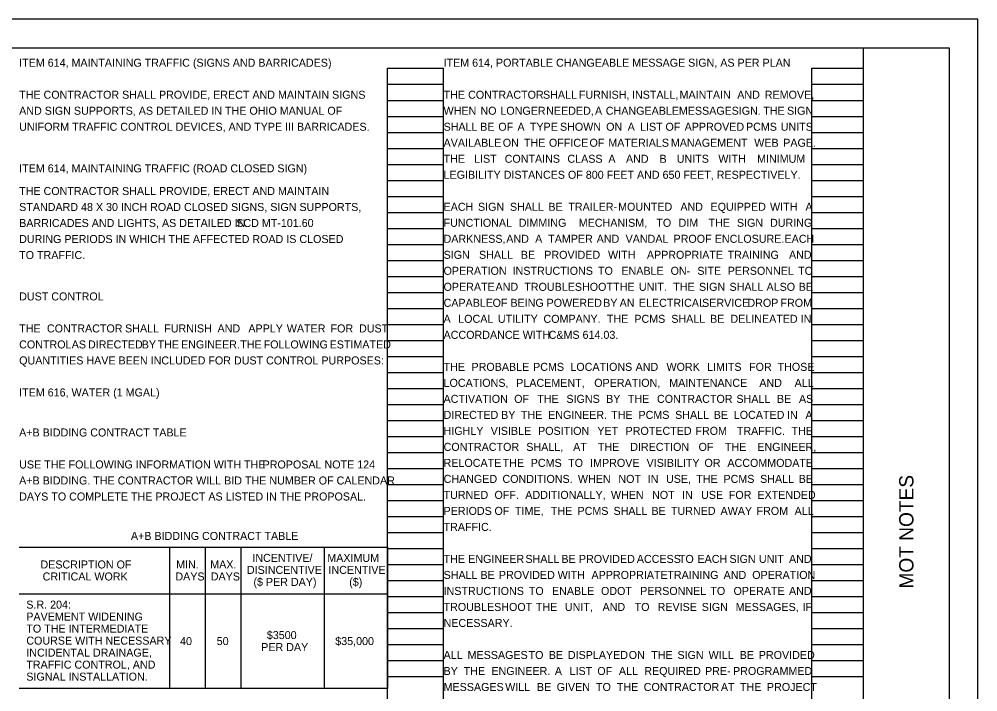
# Model space of a CAD drawing. Extents: x 0 to 34, y 0 to 22.
# Drawn here: x 17.24 to 34, y 10.23 to 22 of the extents above; entities that cross this region are included whole.
import ezdxf

# ---------------------------------------------------------------- set-up
doc = ezdxf.new("R2010")
doc.units = 0
for name, color, linetype in [('SH_Border', 7, 'Continuous'), ('SH_Cut_Line', 7, 'Continuous'), ('SH_Data', 7, 'Continuous'), ('SH_Text', 7, 'Continuous'), ('TX_P_1', 7, 'Continuous')]:
    doc.layers.add(name, color=color, linetype=linetype)

msp = doc.modelspace()

# ---------------------------------------------------------------- linework, layer by layer
at = {"layer": 'SH_Border'}
msp.add_line((32, 0.5), (32, 21.5), dxfattribs=at)
msp.add_lwpolyline([(1.5, 21.5), (33.5, 21.5), (33.5, 0.5), (1.5, 0.5)], close=True, dxfattribs=at)
at = {"layer": 'SH_Cut_Line'}
msp.add_lwpolyline([(0, 0), (34, 0), (34, 22), (0, 22)], close=True, dxfattribs=at)
at = {"layer": 'SH_Data'}
for p, q in [((23.68, 0.98), (23.68, 21.14)), ((23.68, 21.14), (24.66, 21.14)), ((24.66, 0.98), (24.66, 21.14)), ((31.1, 0.98), (31.1, 21.14)), ((31.1, 21.14), (32, 21.14)), ((32, 0.98), (32, 21.14)), ((23.68, 20.86), (24.66, 20.86)), ((31.1, 20.86), (32, 20.86)), ((23.68, 20.58), (24.66, 20.58)), ((31.1, 20.58), (32, 20.58)), ((23.68, 20.3), (24.66, 20.3)), ((31.1, 20.3), (32, 20.3)), ((23.68, 20.02), (24.66, 20.02)), ((31.1, 20.02), (32, 20.02)), ((23.68, 19.74), (24.66, 19.74)), ((31.1, 19.74), (32, 19.74)), ((23.68, 19.46), (24.66, 19.46)), ((31.1, 19.46), (32, 19.46)), ((23.68, 19.18), (24.66, 19.18)), ((31.1, 19.18), (32, 19.18)), ((23.68, 18.9), (24.66, 18.9)), ((31.1, 18.9), (32, 18.9)), ((23.68, 18.62), (24.66, 18.62)), ((31.1, 18.62), (32, 18.62)), ((23.68, 18.34), (24.66, 18.34)), ((31.1, 18.34), (32, 18.34)), ((23.68, 18.06), (24.66, 18.06)), ((31.1, 18.06), (32, 18.06)), ((23.68, 17.78), (24.66, 17.78)), ((31.1, 17.78), (32, 17.78)), ((23.68, 17.5), (24.66, 17.5)), ((31.1, 17.5), (32, 17.5)), ((23.68, 17.22), (24.66, 17.22)), ((31.1, 17.22), (32, 17.22)), ((23.68, 16.94), (24.66, 16.94)), ((31.1, 16.94), (32, 16.94)), ((23.68, 16.66), (24.66, 16.66)), ((31.1, 16.66), (32, 16.66)), ((23.68, 16.38), (24.66, 16.38)), ((31.1, 16.38), (32, 16.38)), ((23.68, 16.1), (24.66, 16.1)), ((31.1, 16.1), (32, 16.1)), ((23.68, 15.82), (24.66, 15.82)), ((31.1, 15.82), (32, 15.82)), ((23.68, 15.54), (24.66, 15.54)), ((31.1, 15.54), (32, 15.54)), ((23.68, 15.26), (24.66, 15.26)), ((31.1, 15.26), (32, 15.26)), ((23.68, 14.98), (24.66, 14.98)), ((31.1, 14.98), (32, 14.98)), ((23.68, 14.7), (24.66, 14.7)), ((31.1, 14.7), (32, 14.7)), ((23.68, 14.42), (24.66, 14.42)), ((31.1, 14.42), (32, 14.42)), ((23.68, 14.14), (24.66, 14.14)), ((31.1, 14.14), (32, 14.14)), ((23.68, 13.86), (24.66, 13.86)), ((31.1, 13.86), (32, 13.86)), ((23.68, 13.58), (24.66, 13.58)), ((31.1, 13.58), (32, 13.58)), ((23.68, 13.3), (24.66, 13.3)), ((31.1, 13.3), (32, 13.3)), ((23.68, 13.02), (24.66, 13.02)), ((31.1, 13.02), (32, 13.02)), ((23.68, 12.74), (24.66, 12.74)), ((31.1, 12.74), (32, 12.74)), ((23.68, 12.46), (24.66, 12.46)), ((31.1, 12.46), (32, 12.46)), ((23.68, 12.18), (24.66, 12.18)), ((31.1, 12.18), (32, 12.18)), ((23.68, 11.9), (24.66, 11.9)), ((31.1, 11.9), (32, 11.9)), ((23.68, 11.62), (24.66, 11.62)), ((31.1, 11.62), (32, 11.62)), ((23.68, 11.34), (24.66, 11.34)), ((31.1, 11.34), (32, 11.34)), ((23.68, 11.06), (24.66, 11.06)), ((31.1, 11.06), (32, 11.06)), ((23.68, 10.78), (24.66, 10.78)), ((31.1, 10.78), (32, 10.78)), ((23.68, 10.5), (24.66, 10.5)), ((31.1, 10.5), (32, 10.5))]:
    msp.add_line(p, q, dxfattribs=at)
at = {"layer": 'SH_Text'}
msp.add_line((17.24, 11.949), (23.68, 11.949), dxfattribs=at)
for points in [[(17.24, 12.764), (23.68, 12.764), (23.68, 10.294), (17.24, 10.294)], [(19.877, 10.294), (19.877, 12.264), (19.877, 12.764)], [(20.499, 10.294), (20.499, 12.264), (20.499, 12.764)], [(21.122, 10.294), (21.122, 12.264), (21.122, 12.764)], [(22.577, 10.294), (22.577, 12.264), (22.577, 12.764)]]:
    msp.add_lwpolyline(points, dxfattribs=at)

# ---------------------------------------------------------------- texts
at = {"layer": 'SH_Data'}
msp.add_text('MOT NOTES', height=0.25, rotation=90, dxfattribs=at).set_placement((32.875, 12.04))
at = {"layer": 'SH_Text'}
for s, p in [('ITEM 614, MAINTAINING TRAFFIC (SIGNS AND BARRICADES)', (17.24, 21.168)), ('ITEM 614, PORTABLE CHANGEABLE MESSAGE SIGN, AS PER PLAN', (24.66, 21.168)), ('THE CONTRACTOR SHALL PROVIDE, ERECT AND MAINTAIN SIGNS', (17.24, 20.608)), ('THE ', (24.66, 20.608)), ('CONTRACTOR ', (25.089, 20.608)), ('SHALL ', (26.398, 20.608)), ('FURNISH, ', (27.025, 20.608)), ('INSTALL, ', (27.954, 20.608)), ('MAINTAIN ', (28.786, 20.608)), ('AND ', (29.794, 20.608)), ('REMOVE, ', (30.276, 20.608)), ('AND SIGN SUPPORTS, AS DETAILED IN THE OHIO MANUAL OF', (17.24, 20.328)), ('WHEN ', (24.66, 20.328)), ('NO ', (25.305, 20.328)), ('LONGER ', (25.653, 20.328)), ('NEEDED, ', (26.454, 20.328)), ('A ', (27.307, 20.328)), ('CHANGEABLE ', (27.496, 20.328)), ('MESSAGE ', (28.773, 20.328)), ('SIGN. ', (29.696, 20.328)), ('THE ', (30.25, 20.328)), ('SIGN ', (30.664, 20.328)), ('UNIFORM TRAFFIC CONTROL DEVICES, AND TYPE III BARRICADES.', (17.24, 20.048)), ('SHALL ', (24.66, 20.048)), ('BE ', (25.3, 20.048)), ('OF ', (25.617, 20.048)), ('A ', (25.952, 20.048)), ('TYPE ', (26.169, 20.048)), ('SHOWN ', (26.695, 20.048)), ('ON ', (27.502, 20.048)), ('A ', (27.878, 20.048)), ('LIST ', (28.095, 20.048)), ('OF ', (28.539, 20.048)), ('APPROVED ', (28.874, 20.048)), ('PCMS ', (29.947, 20.048)), ('UNITS ', (30.554, 20.048)), ('AVAILABLE ', (24.66, 19.768)), ('ON ', (25.695, 19.768)), ('THE ', (26.065, 19.768)), ('OFFICE ', (26.502, 19.768)), ('OF ', (27.211, 19.768)), ('MATERIALS ', (27.54, 19.768)), ('MANAGEMENT ', (28.633, 19.768)), ('WEB ', (30.091, 19.768)), ('PAGE. ', (30.598, 19.768)), ('THE ', (24.66, 19.488)), ('LIST ', (25.193, 19.488)), ('CONTAINS ', (25.728, 19.488)), ('CLASS ', (26.825, 19.488)), ('A ', (27.541, 19.488)), ('AND ', (27.849, 19.488)), ('B ', (28.435, 19.488)), ('UNITS ', (28.736, 19.488)), ('WITH ', (29.464, 19.488)), ('MINIMUM ', (30.141, 19.488)), ('ITEM 614, MAINTAINING TRAFFIC (ROAD CLOSED SIGN)', (17.24, 19.32)), ('LEGIBILITY DISTANCES OF 800 FEET AND 650 FEET, RESPECTIVELY.', (24.66, 19.208)), ('THE CONTRACTOR SHALL PROVIDE, ERECT AND MAINTAIN', (17.24, 18.924)), ('STANDARD 48 X 30 INCH ROAD CLOSED SIGNS, SIGN SUPPORTS,', (17.24, 18.644)), ('EACH ', (24.66, 18.648)), ('SIGN ', (25.262, 18.648)), ('SHALL ', (25.82, 18.648)), ('BE ', (26.492, 18.648)), ('TRAILER-', (26.841, 18.648)), ('MOUNTED ', (27.711, 18.648)), ('AND ', (28.8, 18.648)), ('EQUIPPED ', (29.327, 18.648)), ('WITH ', (30.367, 18.648)), ('A ', (30.986, 18.648)), ('BARRICADES AND LIGHTS, AS DETAILED IN ', (17.24, 18.364)), ('SCD MT-101.60 ', (21.035, 18.364)), ('FUNCTIONAL ', (24.66, 18.368)), ('DIMMING ', (25.974, 18.368)), ('MECHANISM, ', (27.023, 18.368)), ('TO ', (28.38, 18.368)), ('DIM ', (28.769, 18.368)), ('THE ', (29.292, 18.368)), ('SIGN ', (29.788, 18.368)), ('DURING ', (30.367, 18.368)), ('DURING PERIODS IN WHICH THE AFFECTED ROAD IS CLOSED', (17.24, 18.084)), ('DARKNESS, ', (24.66, 18.088)), ('AND ', (25.756, 18.088)), ('A ', (26.261, 18.088)), ('TAMPER ', (26.489, 18.088)), ('AND ', (27.337, 18.088)), ('VANDAL ', (27.842, 18.088)), ('PROOF ', (28.68, 18.088)), ('ENCLOSURE. ', (29.401, 18.088)), ('EACH ', (30.621, 18.088)), ('TO TRAFFIC.', (17.24, 17.804)), ('SIGN ', (24.66, 17.808)), ('SHALL ', (25.279, 17.808)), ('BE ', (26.011, 17.808)), ('PROVIDED ', (26.42, 17.808)), ('WITH ', (27.535, 17.808)), ('APPROPRIATE ', (28.214, 17.808)), ('TRAINING ', (29.627, 17.808)), ('AND ', (30.699, 17.808)), ('OPERATION ', (24.66, 17.528)), ('INSTRUCTIONS ', (25.867, 17.528)), ('TO ', (27.36, 17.528)), ('ENABLE ', (27.769, 17.528)), ('ON-', (28.629, 17.528)), ('SITE ', (29.096, 17.528)), ('PERSONNEL ', (29.629, 17.528)), ('TO ', (30.858, 17.528)), ('OPERATE ', (24.66, 17.248)), ('AND ', (25.568, 17.248)), ('TROUBLESHOOT ', (26.071, 17.248)), ('THE ', (27.625, 17.248)), ('UNIT. ', (28.075, 17.248)), ('THE ', (28.675, 17.248)), ('SIGN ', (29.125, 17.248)), ('SHALL ', (29.659, 17.248)), ('ALSO ', (30.306, 17.248)), ('BE ', (30.868, 17.248)), ('DUST CONTROL', (17.24, 17.08)), ('CAPABLE ', (24.66, 16.968)), ('OF ', (25.517, 16.968)), ('BEING ', (25.829, 16.968)), ('POWERED ', (26.461, 16.968)), ('BY ', (27.45, 16.968)), ('AN ', (27.738, 16.968)), ('ELECTRICAL ', (28.074, 16.968)), ('SERVICE ', (29.18, 16.968)), ('DROP ', (29.972, 16.968)), ('FROM ', (30.55, 16.968)), ('A ', (24.66, 16.688)), ('LOCAL ', (24.916, 16.688)), ('UTILITY ', (25.61, 16.688)), ('COMPANY. ', (26.406, 16.688)), ('THE ', (27.514, 16.688)), ('PCMS ', (27.995, 16.688)), ('SHALL ', (28.641, 16.688)), ('BE ', (29.319, 16.688)), ('DELINEATED ', (29.675, 16.688)), ('IN ', (30.903, 16.688)), ('THE ', (17.24, 16.52)), ('CONTRACTOR ', (17.726, 16.52)), ('SHALL ', (19.092, 16.52)), ('FURNISH ', (19.776, 16.52)), ('AND ', (20.708, 16.52)), ('APPLY ', (21.247, 16.52)), ('WATER ', (21.919, 16.52)), ('FOR ', (22.684, 16.52)), ('DUST ', (23.182, 16.52)), ('ACCORDANCE WITH ', (24.66, 16.408)), ('C&MS 614.03.', (26.497, 16.408)), ('CONTROL ', (17.24, 16.24)), ('AS ', (18.159, 16.24)), ('DIRECTED ', (18.443, 16.24)), ('BY ', (19.383, 16.24)), ('THE ', (19.661, 16.24)), ('ENGINEER. ', (20.07, 16.24)), ('THE ', (21.105, 16.24)), ('FOLLOWING ', (21.514, 16.24)), ('ESTIMATED ', (22.668, 16.24)), ('QUANTITIES HAVE BEEN INCLUDED FOR DUST CONTROL PURPOSES:', (17.24, 15.96)), ('THE ', (24.66, 15.848)), ('PROBABLE ', (25.148, 15.848)), ('PCMS ', (26.225, 15.848)), ('LOCATIONS ', (26.877, 15.848)), ('AND ', (28.017, 15.848)), ('WORK ', (28.557, 15.848)), ('LIMITS ', (29.266, 15.848)), ('FOR ', (30.001, 15.848)), ('THOSE ', (30.499, 15.848)), ('LOCATIONS, ', (24.66, 15.568)), ('PLACEMENT, ', (25.93, 15.568)), ('OPERATION, ', (27.294, 15.568)), ('MAINTENANCE ', (28.605, 15.568)), ('AND ', (30.18, 15.568)), ('ALL ', (30.797, 15.568)), ('ITEM 616, WATER (1 MGAL)', (17.24, 15.4)), ('ACTIVATION ', (24.66, 15.288)), ('OF ', (25.894, 15.288)), ('THE ', (26.298, 15.288)), ('SIGNS ', (26.808, 15.288)), ('BY ', (27.502, 15.288)), ('THE ', (27.881, 15.288)), ('CONTRACTOR ', (28.391, 15.288)), ('SHALL ', (29.78, 15.288)), ('BE ', (30.488, 15.288)), ('AS ', (30.873, 15.288)), ('DIRECTED ', (24.66, 15.008)), ('BY ', (25.666, 15.008)), ('THE ', (26.012, 15.008)), ('ENGINEER. ', (26.488, 15.008)), ('THE ', (27.59, 15.008)), ('PCMS ', (28.067, 15.008)), ('SHALL ', (28.708, 15.008)), ('BE ', (29.382, 15.008)), ('LOCATED ', (29.734, 15.008)), ('IN ', (30.664, 15.008)), ('A ', (30.986, 15.008)), ('A+B BIDDING CONTRACT TABLE', (17.24, 14.7)), ('HIGHLY ', (24.66, 14.728)), ('VISIBLE ', (25.484, 14.728)), ('POSITION ', (26.312, 14.728)), ('YET ', (27.348, 14.728)), ('PROTECTED ', (27.842, 14.728)), ('FROM ', (29.063, 14.728)), ('TRAFFIC. ', (29.787, 14.728)), ('THE ', (30.743, 14.728)), ('CONTRACTOR ', (24.66, 14.448)), ('SHALL, ', (26.106, 14.448)), ('AT ', (26.925, 14.448)), ('THE ', (27.356, 14.448)), ('DIRECTION ', (27.923, 14.448)), ('OF ', (29.118, 14.448)), ('THE ', (29.578, 14.448)), ('ENGINEER, ', (30.145, 14.448)), ('USE THE FOLLOWING INFORMATION WITH THE ', (17.24, 14.14)), ('PROPOSAL NOTE 124', (21.496, 14.14)), ('RELOCATE ', (24.66, 14.168)), ('THE ', (25.694, 14.168)), ('PCMS ', (26.184, 14.168)), ('TO ', (26.838, 14.168)), ('IMPROVE ', (27.222, 14.168)), ('VISIBILITY ', (28.209, 14.168)), ('OR ', (29.221, 14.168)), ('ACCOMMODATE ', (29.622, 14.168)), ('A+B BIDDING. THE CONTRACTOR WILL BID THE NUMBER OF CALENDAR', (17.24, 13.86)), ('CHANGED ', (24.66, 13.888)), ('CONDITIONS. ', (25.689, 13.888)), ('WHEN ', (27.009, 13.888)), ('NOT ', (27.716, 13.888)), ('IN ', (28.228, 13.888)), ('USE, ', (28.549, 13.888)), ('THE ', (29.077, 13.888)), ('PCMS ', (29.553, 13.888)), ('SHALL ', (30.194, 13.888)), ('BE ', (30.868, 13.888)), ('TURNED ', (24.66, 13.608)), ('OFF. ', (25.55, 13.608)), ('ADDITIONALLY, ', (26.088, 13.608)), ('WHEN ', (27.586, 13.608)), ('NOT ', (28.305, 13.608)), ('IN ', (28.829, 13.608)), ('USE ', (29.162, 13.608)), ('FOR ', (29.647, 13.608)), ('EXTENDED ', (30.146, 13.608)), ('DAYS TO COMPLETE THE PROJECT AS LISTED IN THE PROPOSAL.', (17.24, 13.58)), ('PERIODS ', (24.66, 13.328)), ('OF ', (25.55, 13.328)), ('TIME, ', (25.908, 13.328)), ('THE ', (26.535, 13.328)), ('PCMS ', (27.001, 13.328)), ('SHALL ', (27.631, 13.328)), ('BE ', (28.294, 13.328)), ('TURNED ', (28.635, 13.328)), ('AWAY ', (29.502, 13.328)), ('FROM ', (30.132, 13.328)), ('ALL ', (30.797, 13.328)), ('TRAFFIC. ', (24.66, 13.048)), ('A+B BIDDING CONTRACT TABLE', (19.194, 12.89)), ('INCENTIVE/', (21.317, 12.506)), ('MAXIMUM', (22.627, 12.506)), ('THE ', (24.66, 12.488)), ('ENGINEER ', (25.091, 12.488)), ('SHALL ', (26.091, 12.488)), ('BE ', (26.72, 12.488)), ('PROVIDED ', (27.026, 12.488)), ('ACCESS ', (28.038, 12.488)), ('TO ', (28.774, 12.488)), ('EACH ', (29.099, 12.488)), ('SIGN ', (29.658, 12.488)), ('UNIT ', (30.173, 12.488)), ('AND ', (30.699, 12.488)), ('DESCRIPTION OF ', (17.612, 12.391)), ('MIN.', (19.985, 12.391)), ('MAX.', (20.581, 12.391)), ('DISINCENTIVE', (21.222, 12.296)), ('INCENTIVE', (22.647, 12.296)), ('CRITICAL WORK', (17.65, 12.181)), ('DAYS', (19.971, 12.181)), ('DAYS', (20.59, 12.181)), ('($ PER DAY)', (21.336, 12.086)), ('($)', (23.01, 12.086)), ('SHALL ', (24.66, 12.208)), ('BE ', (25.305, 12.208)), ('PROVIDED ', (25.627, 12.208)), ('WITH ', (26.654, 12.208)), ('APPROPRIATE ', (27.246, 12.208)), ('TRAINING ', (28.572, 12.208)), ('AND ', (29.556, 12.208)), ('OPERATION ', (30.056, 12.208)), ('INSTRUCTIONS ', (24.66, 11.928)), ('TO ', (26.15, 11.928)), ('ENABLE ', (26.555, 11.928)), ('ODOT ', (27.412, 11.928)), ('PERSONNEL ', (28.097, 11.928)), ('TO ', (29.324, 11.928)), ('OPERATE ', (29.729, 11.928)), ('AND ', (30.699, 11.928)), ('TROUBLESHOOT ', (24.66, 11.648)), ('THE ', (26.273, 11.648)), ('UNIT, ', (26.781, 11.648)), ('AND ', (27.439, 11.648)), ('TO ', (28, 11.648)), ('REVISE ', (28.402, 11.648)), ('SIGN ', (29.173, 11.648)), ('MESSAGES, ', (29.766, 11.648)), ('IF ', (30.936, 11.648)), ('NECESSARY.', (24.66, 11.368)), ('$3500', (21.57, 11.156)), ('40', (20.053, 11.051)), ('50', (20.694, 11.051)), ('PER DAY', (21.472, 10.946)), ('$35,000', (22.766, 11.051)), ('ALL ', (24.66, 10.808)), ('MESSAGES ', (25.08, 10.808)), ('TO ', (26.146, 10.808)), ('BE ', (26.499, 10.808)), ('DISPLAYED ', (26.833, 10.808)), ('ON ', (27.897, 10.808)), ('THE ', (28.29, 10.808)), ('SIGN ', (28.749, 10.808)), ('WILL ', (29.293, 10.808)), ('BE ', (29.837, 10.808)), ('PROVIDED ', (30.171, 10.808)), ('BY ', (24.66, 10.528)), ('THE ', (25.012, 10.528)), ('ENGINEER. ', (25.496, 10.528)), ('A ', (26.605, 10.528)), ('LIST ', (26.863, 10.528)), ('OF ', (27.348, 10.528)), ('ALL ', (27.725, 10.528)), ('REQUIRED ', (28.169, 10.528)), ('PRE-', (29.231, 10.528)), ('PROGRAMMED ', (29.721, 10.528)), ('MESSAGES ', (24.66, 10.248)), ('WILL ', (25.737, 10.248)), ('BE ', (26.292, 10.248)), ('GIVEN ', (26.637, 10.248)), ('TO ', (27.325, 10.248)), ('THE ', (27.689, 10.248)), ('CONTRACTOR ', (28.159, 10.248)), ('AT ', (29.508, 10.248)), ('THE ', (29.843, 10.248)), ('PROJECT ', (30.313, 10.248))]:
    msp.add_text(s, height=0.14, dxfattribs=at).set_placement(p)
at = {"layer": 'TX_P_1'}
for s, p in [('S.R. 204:', (17.365, 11.689)), ('PAVEMENT WIDENING', (17.365, 11.479)), ('TO THE INTERMEDIATE', (17.365, 11.269)), ('COURSE WITH NECESSARY', (17.365, 11.059)), ('INCIDENTAL DRAINAGE,', (17.365, 10.849)), ('TRAFFIC CONTROL, AND', (17.365, 10.639)), ('SIGNAL INSTALLATION.', (17.365, 10.429))]:
    msp.add_text(s, height=0.14, rotation=360, dxfattribs=at).set_placement(p)

doc.saveas('drawing.dxf')
